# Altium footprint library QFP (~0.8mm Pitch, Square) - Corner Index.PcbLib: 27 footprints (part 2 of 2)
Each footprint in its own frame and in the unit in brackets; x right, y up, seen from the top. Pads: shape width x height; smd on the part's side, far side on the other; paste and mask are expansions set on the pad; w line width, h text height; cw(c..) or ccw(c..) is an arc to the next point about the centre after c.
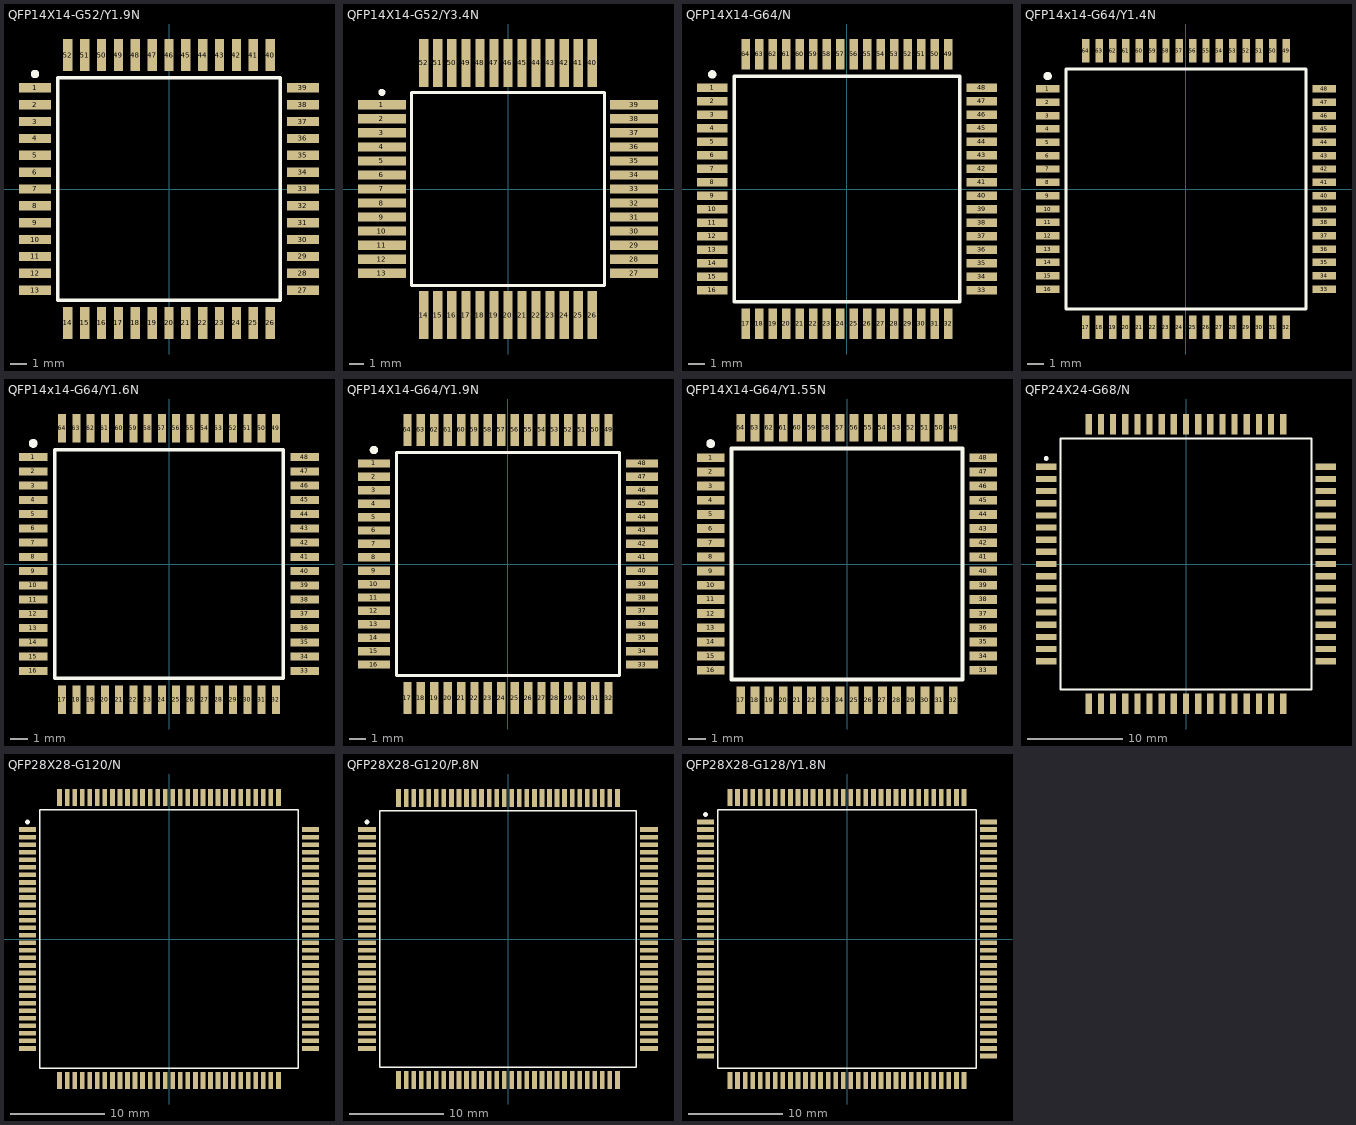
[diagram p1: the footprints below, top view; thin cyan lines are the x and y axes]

## QFP14X14-G52/Y1.9N [mm]
pads (52):
  rect 1.9x0.55 smd: 1(-7.95,6) 2(-7.95,5) 3(-7.95,4) 4(-7.95,3) 5(-7.95,2) 6(-7.95,1) 7(-7.95,0) 8(-7.95,-1) 9(-7.95,-2) 10(-7.95,-3) 11(-7.95,-4) 12(-7.95,-5) 13(-7.95,-6) 27(7.95,-6) 28(7.95,-5) 29(7.95,-4) 30(7.95,-3) 31(7.95,-2) 32(7.95,-1) 33(7.95,0) 34(7.95,1) 35(7.95,2) 36(7.95,3) 37(7.95,4) 38(7.95,5) 39(7.95,6)
  rect 0.55x1.9 smd: 14(-6,-7.95) 15(-5,-7.95) 16(-4,-7.95) 17(-3,-7.95) 18(-2,-7.95) 19(-1,-7.95) 20(0,-7.95) 21(1,-7.95) 22(2,-7.95) 23(3,-7.95) 24(4,-7.95) 25(5,-7.95) 26(6,-7.95) 40(6,7.95) 41(5,7.95) 42(4,7.95) 43(3,7.95) 44(2,7.95) 45(1,7.95) 46(0,7.95) 47(-1,7.95) 48(-2,7.95) 49(-3,7.95) 50(-4,7.95) 51(-5,7.95) 52(-6,7.95)
Top Overlay:
  circle w0.25: c-7.95,6.825 r0.125
  lines w0.2: -6.6,-6.6 6.6,-6.6 6.6,6.6 -6.6,6.6 -6.6,-6.6

## QFP14X14-G52/Y3.4N [mm]
pads (52):
  rect 3.4x0.65 smd: 1(-8.975,6) 2(-8.975,5) 3(-8.975,4) 4(-8.975,3) 5(-8.975,2) 6(-8.975,1) 7(-8.975,0) 8(-8.975,-1) 9(-8.975,-2) 10(-8.975,-3) 11(-8.975,-4) 12(-8.975,-5) 13(-8.975,-6) 27(8.975,-6) 28(8.975,-5) 29(8.975,-4) 30(8.975,-3) 31(8.975,-2) 32(8.975,-1) 33(8.975,0) 34(8.975,1) 35(8.975,2) 36(8.975,3) 37(8.975,4) 38(8.975,5) 39(8.975,6)
  rect 0.65x3.4 smd: 14(-6,-8.975) 15(-5,-8.975) 16(-4,-8.975) 17(-3,-8.975) 18(-2,-8.975) 19(-1,-8.975) 20(0,-8.975) 21(1,-8.975) 22(2,-8.975) 23(3,-8.975) 24(4,-8.975) 25(5,-8.975) 26(6,-8.975) 40(6,8.975) 41(5,8.975) 42(4,8.975) 43(3,8.975) 44(2,8.975) 45(1,8.975) 46(0,8.975) 47(-1,8.975) 48(-2,8.975) 49(-3,8.975) 50(-4,8.975) 51(-5,8.975) 52(-6,8.975)
Top Overlay:
  circle w0.25: c-8.975,6.875 r0.125
  lines w0.2: -6.875,-6.875 -6.875,6.875 6.875,6.875 6.875,-6.875 -6.875,-6.875

## QFP14X14-G64/N [mm]
pads (64):
  rect 1.8x0.5 smd: 1(-8,6) 2(-8,5.2) 3(-8,4.4) 4(-8,3.6) 5(-8,2.8) 6(-8,2) 7(-8,1.2) 8(-8,0.4) 9(-8,-0.4) 10(-8,-1.2) 11(-8,-2) 12(-8,-2.8) 13(-8,-3.6) 14(-8,-4.4) 15(-8,-5.2) 16(-8,-6) 33(8,-6) 34(8,-5.2) 35(8,-4.4) 36(8,-3.6) 37(8,-2.8) 38(8,-2) 39(8,-1.2) 40(8,-0.4) 41(8,0.4) 42(8,1.2) 43(8,2) 44(8,2.8) 45(8,3.6) 46(8,4.4) 47(8,5.2) 48(8,6)
  rect 0.5x1.8 smd: 17(-6,-8) 18(-5.2,-8) 19(-4.4,-8) 20(-3.6,-8) 21(-2.8,-8) 22(-2,-8) 23(-1.2,-8) 24(-0.4,-8) 25(0.4,-8) 26(1.2,-8) 27(2,-8) 28(2.8,-8) 29(3.6,-8) 30(4.4,-8) 31(5.2,-8) 32(6,-8) 49(6,8) 50(5.2,8) 51(4.4,8) 52(3.6,8) 53(2.8,8) 54(2,8) 55(1.2,8) 56(0.4,8) 57(-0.4,8) 58(-1.2,8) 59(-2,8) 60(-2.8,8) 61(-3.6,8) 62(-4.4,8) 63(-5.2,8) 64(-6,8)
Top Overlay:
  circle w0.25: c-8,6.8 r0.125
  lines w0.2: -6.7,-6.7 6.7,-6.7 6.7,6.7 -6.7,6.7 -6.7,-6.7

## QFP14x14-G64/Y1.4N [mm]
pads (64):
  rect 1.4x0.45 smd: 1(-8.3,6) 2(-8.3,5.2) 3(-8.3,4.4) 4(-8.3,3.6) 5(-8.3,2.8) 6(-8.3,2) 7(-8.3,1.2) 8(-8.3,0.4) 9(-8.3,-0.4) 10(-8.3,-1.2) 11(-8.3,-2) 12(-8.3,-2.8) 13(-8.3,-3.6) 14(-8.3,-4.4) 15(-8.3,-5.2) 16(-8.3,-6) 33(8.3,-6) 34(8.3,-5.2) 35(8.3,-4.4) 36(8.3,-3.6) 37(8.3,-2.8) 38(8.3,-2) 39(8.3,-1.2) 40(8.3,-0.4) 41(8.3,0.4) 42(8.3,1.2) 43(8.3,2) 44(8.3,2.8) 45(8.3,3.6) 46(8.3,4.4) 47(8.3,5.2) 48(8.3,6)
  rect 0.45x1.4 smd: 17(-6,-8.3) 18(-5.2,-8.3) 19(-4.4,-8.3) 20(-3.6,-8.3) 21(-2.8,-8.3) 22(-2,-8.3) 23(-1.2,-8.3) 24(-0.4,-8.3) 25(0.4,-8.3) 26(1.2,-8.3) 27(2,-8.3) 28(2.8,-8.3) 29(3.6,-8.3) 30(4.4,-8.3) 31(5.2,-8.3) 32(6,-8.3) 49(6,8.3) 50(5.2,8.3) 51(4.4,8.3) 52(3.6,8.3) 53(2.8,8.3) 54(2,8.3) 55(1.2,8.3) 56(0.4,8.3) 57(-0.4,8.3) 58(-1.2,8.3) 59(-2,8.3) 60(-2.8,8.3) 61(-3.6,8.3) 62(-4.4,8.3) 63(-5.2,8.3) 64(-6,8.3)
Top Overlay:
  circle w0.25: c-8.3,6.775 r0.125
  lines w0.2: -7.2,-7.2 7.2,-7.2 7.2,7.2 -7.2,7.2 -7.2,-7.2

## QFP14x14-G64/Y1.6N [mm]
pads (64):
  rect 1.6x0.45 smd: 1(-7.625,6) 2(-7.625,5.2) 3(-7.625,4.4) 4(-7.625,3.6) 5(-7.625,2.8) 6(-7.625,2) 7(-7.625,1.2) 8(-7.625,0.4) 9(-7.625,-0.4) 10(-7.625,-1.2) 11(-7.625,-2) 12(-7.625,-2.8) 13(-7.625,-3.6) 14(-7.625,-4.4) 15(-7.625,-5.2) 16(-7.625,-6) 33(7.625,-6) 34(7.625,-5.2) 35(7.625,-4.4) 36(7.625,-3.6) 37(7.625,-2.8) 38(7.625,-2) 39(7.625,-1.2) 40(7.625,-0.4) 41(7.625,0.4) 42(7.625,1.2) 43(7.625,2) 44(7.625,2.8) 45(7.625,3.6) 46(7.625,4.4) 47(7.625,5.2) 48(7.625,6)
  rect 0.45x1.6 smd: 17(-6,-7.625) 18(-5.2,-7.625) 19(-4.4,-7.625) 20(-3.6,-7.625) 21(-2.8,-7.625) 22(-2,-7.625) 23(-1.2,-7.625) 24(-0.4,-7.625) 25(0.4,-7.625) 26(1.2,-7.625) 27(2,-7.625) 28(2.8,-7.625) 29(3.6,-7.625) 30(4.4,-7.625) 31(5.2,-7.625) 32(6,-7.625) 49(6,7.625) 50(5.2,7.625) 51(4.4,7.625) 52(3.6,7.625) 53(2.8,7.625) 54(2,7.625) 55(1.2,7.625) 56(0.4,7.625) 57(-0.4,7.625) 58(-1.2,7.625) 59(-2,7.625) 60(-2.8,7.625) 61(-3.6,7.625) 62(-4.4,7.625) 63(-5.2,7.625) 64(-6,7.625)
Top Overlay:
  circle w0.25: c-7.625,6.775 r0.125
  lines w0.2: -6.425,-6.425 6.425,-6.425 6.425,6.425 -6.425,6.425 -6.425,-6.425

## QFP14X14-G64/Y1.9N [mm]
pads (64):
  rect 1.9x0.5 smd: 1(-8,6) 2(-8,5.2) 3(-8,4.4) 4(-8,3.6) 5(-8,2.8) 6(-8,2) 7(-8,1.2) 8(-8,0.4) 9(-8,-0.4) 10(-8,-1.2) 11(-8,-2) 12(-8,-2.8) 13(-8,-3.6) 14(-8,-4.4) 15(-8,-5.2) 16(-8,-6) 33(8,-6) 34(8,-5.2) 35(8,-4.4) 36(8,-3.6) 37(8,-2.8) 38(8,-2) 39(8,-1.2) 40(8,-0.4) 41(8,0.4) 42(8,1.2) 43(8,2) 44(8,2.8) 45(8,3.6) 46(8,4.4) 47(8,5.2) 48(8,6)
  rect 0.5x1.9 smd: 17(-6,-8) 18(-5.2,-8) 19(-4.4,-8) 20(-3.6,-8) 21(-2.8,-8) 22(-2,-8) 23(-1.2,-8) 24(-0.4,-8) 25(0.4,-8) 26(1.2,-8) 27(2,-8) 28(2.8,-8) 29(3.6,-8) 30(4.4,-8) 31(5.2,-8) 32(6,-8) 49(6,8) 50(5.2,8) 51(4.4,8) 52(3.6,8) 53(2.8,8) 54(2,8) 55(1.2,8) 56(0.4,8) 57(-0.4,8) 58(-1.2,8) 59(-2,8) 60(-2.8,8) 61(-3.6,8) 62(-4.4,8) 63(-5.2,8) 64(-6,8)
Top Overlay:
  circle w0.25: c-8,6.8 r0.125
  lines w0.2: -6.65,-6.65 6.65,-6.65 6.65,6.65 -6.65,6.65 -6.65,-6.65

## QFP14X14-G64/Y1.55N [mm]
pads (64):
  rect 1.55x0.5 smd: 1(-7.7,6) 2(-7.7,5.2) 3(-7.7,4.4) 4(-7.7,3.6) 5(-7.7,2.8) 6(-7.7,2) 7(-7.7,1.2) 8(-7.7,0.4) 9(-7.7,-0.4) 10(-7.7,-1.2) 11(-7.7,-2) 12(-7.7,-2.8) 13(-7.7,-3.6) 14(-7.7,-4.4) 15(-7.7,-5.2) 16(-7.7,-6) 33(7.7,-6) 34(7.7,-5.2) 35(7.7,-4.4) 36(7.7,-3.6) 37(7.7,-2.8) 38(7.7,-2) 39(7.7,-1.2) 40(7.7,-0.4) 41(7.7,0.4) 42(7.7,1.2) 43(7.7,2) 44(7.7,2.8) 45(7.7,3.6) 46(7.7,4.4) 47(7.7,5.2) 48(7.7,6)
  rect 0.5x1.55 smd: 17(-6,-7.7) 18(-5.2,-7.7) 19(-4.4,-7.7) 20(-3.6,-7.7) 21(-2.8,-7.7) 22(-2,-7.7) 23(-1.2,-7.7) 24(-0.4,-7.7) 25(0.4,-7.7) 26(1.2,-7.7) 27(2,-7.7) 28(2.8,-7.7) 29(3.6,-7.7) 30(4.4,-7.7) 31(5.2,-7.7) 32(6,-7.7) 49(6,7.7) 50(5.2,7.7) 51(4.4,7.7) 52(3.6,7.7) 53(2.8,7.7) 54(2,7.7) 55(1.2,7.7) 56(0.4,7.7) 57(-0.4,7.7) 58(-1.2,7.7) 59(-2,7.7) 60(-2.8,7.7) 61(-3.6,7.7) 62(-4.4,7.7) 63(-5.2,7.7) 64(-6,7.7)
Top Overlay:
  circle w0.25: c-7.7,6.8 r0.125
  lines w0.2: -6.525,-6.525 6.525,-6.525 6.525,6.525 -6.525,6.525 -6.525,-6.525

## QFP24X24-G68/N [mm]
pads (68):
  rect 2.15x0.65 smd: 1(-14.6,10.16) 2(-14.6,8.89) 3(-14.6,7.62) 4(-14.6,6.35) 5(-14.6,5.08) 6(-14.6,3.81) 7(-14.6,2.54) 8(-14.6,1.27) 9(-14.6,0) 10(-14.6,-1.27) 11(-14.6,-2.54) 12(-14.6,-3.81) 13(-14.6,-5.08) 14(-14.6,-6.35) 15(-14.6,-7.62) 16(-14.6,-8.89) 17(-14.6,-10.16) 35(14.6,-10.16) 36(14.6,-8.89) 37(14.6,-7.62) 38(14.6,-6.35) 39(14.6,-5.08) 40(14.6,-3.81) 41(14.6,-2.54) 42(14.6,-1.27) 43(14.6,0) 44(14.6,1.27) 45(14.6,2.54) 46(14.6,3.81) 47(14.6,5.08) 48(14.6,6.35) 49(14.6,7.62) 50(14.6,8.89) 51(14.6,10.16)
  rect 0.65x2.15 smd: 18(-10.16,-14.6) 19(-8.89,-14.6) 20(-7.62,-14.6) 21(-6.35,-14.6) 22(-5.08,-14.6) 23(-3.81,-14.6) 24(-2.54,-14.6) 25(-1.27,-14.6) 26(0,-14.6) 27(1.27,-14.6) 28(2.54,-14.6) 29(3.81,-14.6) 30(5.08,-14.6) 31(6.35,-14.6) 32(7.62,-14.6) 33(8.89,-14.6) 34(10.16,-14.6) 52(10.16,14.6) 53(8.89,14.6) 54(7.62,14.6) 55(6.35,14.6) 56(5.08,14.6) 57(3.81,14.6) 58(2.54,14.6) 59(1.27,14.6) 60(0,14.6) 61(-1.27,14.6) 62(-2.54,14.6) 63(-3.81,14.6) 64(-5.08,14.6) 65(-6.35,14.6) 66(-7.62,14.6) 67(-8.89,14.6) 68(-10.16,14.6)
Top Overlay:
  circle w0.25: c-14.6,11.035 r0.125
  lines w0.2: -13.125,-13.125 13.125,-13.125 13.125,13.125 -13.125,13.125 -13.125,-13.125

## QFP28X28-G120/N [mm]
pads (120):
  rect 1.8x0.5 smd: 1(-15,11.6) 2(-15,10.8) 3(-15,10) 4(-15,9.2) 5(-15,8.4) 6(-15,7.6) 7(-15,6.8) 8(-15,6) 9(-15,5.2) 10(-15,4.4) 11(-15,3.6) 12(-15,2.8) 13(-15,2) 14(-15,1.2) 15(-15,0.4) 16(-15,-0.4) 17(-15,-1.2) 18(-15,-2) 19(-15,-2.8) 20(-15,-3.6) 21(-15,-4.4) 22(-15,-5.2) 23(-15,-6) 24(-15,-6.8) 25(-15,-7.6) 26(-15,-8.4) 27(-15,-9.2) 28(-15,-10) 29(-15,-10.8) 30(-15,-11.6) 61(15,-11.6) 62(15,-10.8) 63(15,-10) 64(15,-9.2) 65(15,-8.4) 66(15,-7.6) 67(15,-6.8) 68(15,-6) 69(15,-5.2) 70(15,-4.4) 71(15,-3.6) 72(15,-2.8) 73(15,-2) 74(15,-1.2) 75(15,-0.4) 76(15,0.4) 77(15,1.2) 78(15,2) 79(15,2.8) 80(15,3.6) 81(15,4.4) 82(15,5.2) 83(15,6) 84(15,6.8) 85(15,7.6) 86(15,8.4) 87(15,9.2) 88(15,10) 89(15,10.8) 90(15,11.6)
  rect 0.5x1.8 smd: 31(-11.6,-15) 32(-10.8,-15) 33(-10,-15) 34(-9.2,-15) 35(-8.4,-15) 36(-7.6,-15) 37(-6.8,-15) 38(-6,-15) 39(-5.2,-15) 40(-4.4,-15) 41(-3.6,-15) 42(-2.8,-15) 43(-2,-15) 44(-1.2,-15) 45(-0.4,-15) 46(0.4,-15) 47(1.2,-15) 48(2,-15) 49(2.8,-15) 50(3.6,-15) 51(4.4,-15) 52(5.2,-15) 53(6,-15) 54(6.8,-15) 55(7.6,-15) 56(8.4,-15) 57(9.2,-15) 58(10,-15) 59(10.8,-15) 60(11.6,-15) 91(11.6,15) 92(10.8,15) 93(10,15) 94(9.2,15) 95(8.4,15) 96(7.6,15) 97(6.8,15) 98(6,15) 99(5.2,15) 100(4.4,15) 101(3.6,15) 102(2.8,15) 103(2,15) 104(1.2,15) 105(0.4,15) 106(-0.4,15) 107(-1.2,15) 108(-2,15) 109(-2.8,15) 110(-3.6,15) 111(-4.4,15) 112(-5.2,15) 113(-6,15) 114(-6.8,15) 115(-7.6,15) 116(-8.4,15) 117(-9.2,15) 118(-10,15) 119(-10.8,15) 120(-11.6,15)
Top Overlay:
  circle w0.25: c-15,12.4 r0.125
  lines w0.2: -13.7,-13.7 13.7,-13.7 13.7,13.7 -13.7,13.7 -13.7,-13.7

## QFP28X28-G120/P.8N [mm]
pads (120):
  rect 1.9x0.5 smd: 1(-14.95,11.6) 2(-14.95,10.8) 3(-14.95,10) 4(-14.95,9.2) 5(-14.95,8.4) 6(-14.95,7.6) 7(-14.95,6.8) 8(-14.95,6) 9(-14.95,5.2) 10(-14.95,4.4) 11(-14.95,3.6) 12(-14.95,2.8) 13(-14.95,2) 14(-14.95,1.2) 15(-14.95,0.4) 16(-14.95,-0.4) 17(-14.95,-1.2) 18(-14.95,-2) 19(-14.95,-2.8) 20(-14.95,-3.6) 21(-14.95,-4.4) 22(-14.95,-5.2) 23(-14.95,-6) 24(-14.95,-6.8) 25(-14.95,-7.6) 26(-14.95,-8.4) 27(-14.95,-9.2) 28(-14.95,-10) 29(-14.95,-10.8) 30(-14.95,-11.6) 61(14.95,-11.6) 62(14.95,-10.8) 63(14.95,-10) 64(14.95,-9.2) 65(14.95,-8.4) 66(14.95,-7.6) 67(14.95,-6.8) 68(14.95,-6) 69(14.95,-5.2) 70(14.95,-4.4) 71(14.95,-3.6) 72(14.95,-2.8) 73(14.95,-2) 74(14.95,-1.2) 75(14.95,-0.4) 76(14.95,0.4) 77(14.95,1.2) 78(14.95,2) 79(14.95,2.8) 80(14.95,3.6) 81(14.95,4.4) 82(14.95,5.2) 83(14.95,6) 84(14.95,6.8) 85(14.95,7.6) 86(14.95,8.4) 87(14.95,9.2) 88(14.95,10) 89(14.95,10.8) 90(14.95,11.6)
  rect 0.5x1.9 smd: 31(-11.6,-14.95) 32(-10.8,-14.95) 33(-10,-14.95) 34(-9.2,-14.95) 35(-8.4,-14.95) 36(-7.6,-14.95) 37(-6.8,-14.95) 38(-6,-14.95) 39(-5.2,-14.95) 40(-4.4,-14.95) 41(-3.6,-14.95) 42(-2.8,-14.95) 43(-2,-14.95) 44(-1.2,-14.95) 45(-0.4,-14.95) 46(0.4,-14.95) 47(1.2,-14.95) 48(2,-14.95) 49(2.8,-14.95) 50(3.6,-14.95) 51(4.4,-14.95) 52(5.2,-14.95) 53(6,-14.95) 54(6.8,-14.95) 55(7.6,-14.95) 56(8.4,-14.95) 57(9.2,-14.95) 58(10,-14.95) 59(10.8,-14.95) 60(11.6,-14.95) 91(11.6,14.95) 92(10.8,14.95) 93(10,14.95) 94(9.2,14.95) 95(8.4,14.95) 96(7.6,14.95) 97(6.8,14.95) 98(6,14.95) 99(5.2,14.95) 100(4.4,14.95) 101(3.6,14.95) 102(2.8,14.95) 103(2,14.95) 104(1.2,14.95) 105(0.4,14.95) 106(-0.4,14.95) 107(-1.2,14.95) 108(-2,14.95) 109(-2.8,14.95) 110(-3.6,14.95) 111(-4.4,14.95) 112(-5.2,14.95) 113(-6,14.95) 114(-6.8,14.95) 115(-7.6,14.95) 116(-8.4,14.95) 117(-9.2,14.95) 118(-10,14.95) 119(-10.8,14.95) 120(-11.6,14.95)
Top Overlay:
  circle w0.25: c-14.95,12.4 r0.125
  lines w0.2: -13.6,-13.6 13.6,-13.6 13.6,13.6 -13.6,13.6 -13.6,-13.6

## QFP28X28-G128/Y1.8N [mm]
pads (128):
  rect 1.8x0.5 smd: 1(-15,12.4) 2(-15,11.6) 3(-15,10.8) 4(-15,10) 5(-15,9.2) 6(-15,8.4) 7(-15,7.6) 8(-15,6.8) 9(-15,6) 10(-15,5.2) 11(-15,4.4) 12(-15,3.6) 13(-15,2.8) 14(-15,2) 15(-15,1.2) 16(-15,0.4) 17(-15,-0.4) 18(-15,-1.2) 19(-15,-2) 20(-15,-2.8) 21(-15,-3.6) 22(-15,-4.4) 23(-15,-5.2) 24(-15,-6) 25(-15,-6.8) 26(-15,-7.6) 27(-15,-8.4) 28(-15,-9.2) 29(-15,-10) 30(-15,-10.8) 31(-15,-11.6) 32(-15,-12.4) 65(15,-12.4) 66(15,-11.6) 67(15,-10.8) 68(15,-10) 69(15,-9.2) 70(15,-8.4) 71(15,-7.6) 72(15,-6.8) 73(15,-6) 74(15,-5.2) 75(15,-4.4) 76(15,-3.6) 77(15,-2.8) 78(15,-2) 79(15,-1.2) 80(15,-0.4) 81(15,0.4) 82(15,1.2) 83(15,2) 84(15,2.8) 85(15,3.6) 86(15,4.4) 87(15,5.2) 88(15,6) 89(15,6.8) 90(15,7.6) 91(15,8.4) 92(15,9.2) 93(15,10) 94(15,10.8) 95(15,11.6) 96(15,12.4)
  rect 0.5x1.8 smd: 33(-12.4,-15) 34(-11.6,-15) 35(-10.8,-15) 36(-10,-15) 37(-9.2,-15) 38(-8.4,-15) 39(-7.6,-15) 40(-6.8,-15) 41(-6,-15) 42(-5.2,-15) 43(-4.4,-15) 44(-3.6,-15) 45(-2.8,-15) 46(-2,-15) 47(-1.2,-15) 48(-0.4,-15) 49(0.4,-15) 50(1.2,-15) 51(2,-15) 52(2.8,-15) 53(3.6,-15) 54(4.4,-15) 55(5.2,-15) 56(6,-15) 57(6.8,-15) 58(7.6,-15) 59(8.4,-15) 60(9.2,-15) 61(10,-15) 62(10.8,-15) 63(11.6,-15) 64(12.4,-15) 97(12.4,15) 98(11.6,15) 99(10.8,15) 100(10,15) 101(9.2,15) 102(8.4,15) 103(7.6,15) 104(6.8,15) 105(6,15) 106(5.2,15) 107(4.4,15) 108(3.6,15) 109(2.8,15) 110(2,15) 111(1.2,15) 112(0.4,15) 113(-0.4,15) 114(-1.2,15) 115(-2,15) 116(-2.8,15) 117(-3.6,15) 118(-4.4,15) 119(-5.2,15) 120(-6,15) 121(-6.8,15) 122(-7.6,15) 123(-8.4,15) 124(-9.2,15) 125(-10,15) 126(-10.8,15) 127(-11.6,15) 128(-12.4,15)
Top Overlay:
  circle w0.25: c-15,13.2 r0.125
  lines w0.2: -13.7,-13.7 13.7,-13.7 13.7,13.7 -13.7,13.7 -13.7,-13.7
